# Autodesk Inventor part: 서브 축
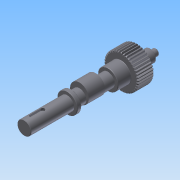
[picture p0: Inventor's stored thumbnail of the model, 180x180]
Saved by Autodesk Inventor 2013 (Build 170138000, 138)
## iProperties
Created: 2016-02
Part Number: 서브 축
Material: 강철, 연강
Document SubType Name: Modeling
Designer: mdu
Categories: <?xml version="1.0" encoding="UTF-16"?> <MemberInstance><Categories><FamilyTemplate><FamilyTemplateParameter ValueType="xs:double" Id="1" ObjectReferenceKey="da
Density: 1 g/cm^3
Mass: 64.1513 g
Surface Area: 165.256 cm^2
Volume: 64.1513 cm^3
CustomPartVersion: 1
Author: mdu
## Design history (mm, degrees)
sketch "Sketch1"
  geometry: C1 r 21 at (0, 0)
  constraints: 1 centre point
  dimensions: "d0" = 42 diameter of C1 (= da_da)
extrude "Extrusion1" new body sketch "Sketch1" distance "d1" = 20 (= da_b); taper "d2" = 0 deg
workplane "Work Plane2"
feature "피치 지름" dims "d4" = 10, "d5" = 0
workplane "Work Plane8"
workplane "Work Plane9"
chamfer "모따기1" distance "d49" = 1; stored, may be unused: second distance "d50" = 2, angle "d51" = 45 deg
sketch "스케치3"
  geometry: C1 r 12.5 at (0, 0); 1 further point
  constraints: 1 centre point, 1 coincident
  dimensions: "d52" = 25 diameter of C1
extrude "돌출2" join sketch "스케치3" distance "d53" = 16; taper "d54" = 0 deg
sketch "스케치4"
  geometry: C1 r 8.5 at (0, 0); 1 further point
  constraints: 1 centre point, 1 coincident
  dimensions: "d55" = 17 diameter of C1
extrude "돌출3" join sketch "스케치4" distance "d56" = 103; taper "d57" = 0 deg
sketch "스케치5"
  geometry: C1 r 7.5 at (0, 0); 1 further point
  constraints: 1 centre point, 1 coincident
  dimensions: "d62" = 15 diameter of C1
extrude "돌출4" join sketch "스케치5" distance "d63" = 16; taper "d64" = 0 deg
sketch "스케치6"
  geometry: C1 r 4 at (0, 0); 1 further point
  constraints: 1 centre point, 1 coincident
  dimensions: "d65" = 8 diameter of C1
extrude "돌출5" join sketch "스케치6" distance "d66" = 7; taper "d67" = 0 deg
chamfer "모따기2" distance "d58" = 0.5; stored, may be unused: second distance "d59" = 2, angle "d60" = 45 deg
fillet "모깎기1" dims "d61" = 0.5
feature "스퍼 기어" dims "da_b" = 20, "da_d" = 40, "da_aw" = 31, "da_da" = 42, "da_df" = 37.5, "da_dw" = 40, angle "da_beta" = 0 deg, "da_lefttooth" = 0, "da_righttooth" = 0
node "작업 평면11"
sketch "스케치7"
  geometry: C1 r 8.5 at (0, 0) reference; C2 r 11.5 at (0, 3); 1 further point
  constraints: 1 centre point, 1 tangent, 1 vertical alignment
  dimensions: "d71" = 3 distance of C2.centre point (0, 0); "d72" = 23 diameter of C2 (derived)
extrude "돌출6" join sketch "스케치7" stored distance "d73" = 20; taper "d74" = 0 deg
node "작업 평면12"
sketch "스케치8"
  geometry: C1 r 12.5 at (0, 0) reference; 1 further point
extrude "돌출7" join sketch "스케치8" distance "d76" = 5; taper "d77" = 0 deg
chamfer "모따기3" distance "d78" = 0.5; stored, may be unused: second distance "d79" = 2, angle "d80" = 45 deg
sketch "스케치9"
  geometry: L1 (-8.5, 86)-(-8.5, 138.5) reference; L2 (-8, 139)-(8, 139) reference; L3 (0, 0)-(0, 139); L4 (-8.5, 115)-(0, 115); L5 (-8.5, 115)-(-8.5, 113.5); L6 (-7, 115)-(-8.5, 113.5)
  constraints: 8 end point, 4 point on line, 1 midpoint, 1 perpendicular
  dimensions: "d81" = 24 distance between parallel lines of L2 L4; "d82" = 45 deg angle of L6 L5; "d83" = 3 diameter of L5.end L4
revolve "회전1" sketch "스케치9" stored, may be unused: angle "d84" = 90 deg
sketch "스케치10"
  geometry: L1 (-8.5, 113.5)-(-7, 115) reference; L2 (-8.5, 116.5)-(-7, 115) reference; 2 further points
  constraints: 1 coincident
node "작업점1"
node "작업 평면14"
sketch "스케치11"
  geometry: L1 (8.5, 102.5)-(-8.5, 102.5) reference; L2 (0, 102.5)-(0, -36); L3 (-2.5, 93.5)-(-2.5, 80.5); L4 (2.5, 80.5)-(2.5, 93.5); L5 (-8, 103)-(8, 103) reference; A1 r 2.5 centre (0, 93.5) between (2.5, 93.5) and (-2.5, 93.5); A2 r 2.5 centre (0, 80.5) between (-2.5, 80.5) and (2.5, 80.5)
  constraints: 6 end point, 4 point on circle, 4 tangent, 2 centre point, 1 midpoint, 1 parallel, 1 perpendicular, 1 point on line, 1 vertical alignment
  dimensions: "d85" = 7 distance edge to line of A1 L5; "d86" = 18 dimension on A2 A1; "d87" = 5 distance between parallel lines of L3 L4
extrude "돌출8" cut sketch "스케치11" distance "d88" = 3; taper "d89" = 0 deg
body "Solid1"
sketch "Sketch2"
  geometry: C1 r 21 at (0, 0) reference; C2 r 20 at (0, 0)
  constraints: 1 centre point, 1 coincident
  dimensions: "d3" = 40 diameter of C2 (= da_dw)
body "Srf1"
other parameters: "d16" = 31 (= da_aw), "d17" = 0, "d34" = 4.5 deg (computed from da_z), "d39" = 0, "d41" = 0, "d43" = 31 (= da_aw), "d46" = 31 (= da_aw), "d47" = 0, "d48" = 0, "d68" = 25
